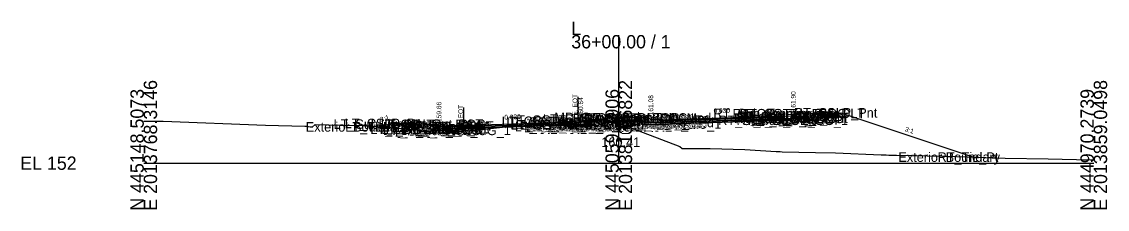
# Model space of a CAD drawing. Extents: x -26 to 4203, y -10 to 9526.
# Drawn here: x 1974.3 to 2202.8, y 5990.3 to 6029.7 of the extents above; entities that cross this region are included whole.
import ezdxf

# ---------------------------------------------------------------- set-up
doc = ezdxf.new("R2010")
doc.units = 0
for name, color, linetype in [('Default', 7, 'Continuous'), ('Exist CMT Pavement', 7, 'Continuous'), ('Exist Cross Section Cell', 7, 'Continuous'), ('Exist XS Center Line Elevation Label', 7, 'Continuous'), ('Exist XS Ground Line', 7, 'Continuous'), ('Prop CMT Conc Surface', 7, 'Continuous'), ('Prop CMT Concrete Structures', 7, 'Continuous'), ('Prop CMT Pvmt Course 1', 7, 'Continuous'), ('Prop CMT Pvmt Course 1 CG', 7, 'Continuous'), ('Prop CMT Pvmt Course 2', 7, 'Continuous'), ('Prop CMT Pvmt Course 3', 7, 'Continuous'), ('Prop CMT Pvmt Surface', 7, 'Continuous'), ('Prop CMT Slope Grass', 7, 'Continuous'), ('Prop CMT Subgrade Earthwork', 7, 'Continuous'), ('Prop XS Hydro Elevations', 7, 'Continuous'), ('Prop XS Label Text', 7, 'Continuous'), ('Prop XS SE Text', 7, 'Continuous'), ('Prop XS Side Slope Text', 7, 'Continuous'), ('Scratch_Level_0', 7, 'Continuous')]:
    doc.layers.add(name, color=color, linetype=linetype)

msp = doc.modelspace()

# ---------------------------------------------------------------- linework, layer by layer
at = {"layer": 'Exist CMT Pavement'}
for p, q in [((2079.53, 6007.97), (2082.4, 6008.24)), ((2082.4, 6008.24), (2085.23, 6008.5)), ((2085.23, 6008.5), (2088.01, 6008.71)), ((2088.01, 6008.71), (2089.25, 6008.81)), ((2067.33, 6006.71), (2068.41, 6006.78)), ((2068.41, 6006.78), (2071.22, 6007.09)), ((2071.22, 6007.09), (2074.28, 6007.44)), ((2074.28, 6007.44), (2076.82, 6007.69)), ((2076.82, 6007.69), (2078.38, 6007.85)), ((2078.38, 6007.85), (2079.53, 6007.97))]:
    msp.add_line(p, q, dxfattribs=at)
at = {"layer": 'Exist Cross Section Cell'}
for p, q in [((2100, 6000), (2100, 6026.93)), ((2000, 6000), (2100, 6000)), ((2100, 6000), (2200, 6000))]:
    msp.add_line(p, q, dxfattribs=at)
at = {"layer": 'Exist XS Ground Line'}
msp.add_lwpolyline([(2000, 6008.86), (2004.08, 6008.8), (2025.6, 6007.99), (2033.9, 6007.77), (2034.25, 6007.76), (2035.46, 6007.59), (2036.06, 6008.11), (2041.35, 6008), (2041.85, 6007.97), (2046.11, 6007.9), (2046.78, 6007.9), (2051.17, 6007.52), (2060.64, 6006.77), (2061.32, 6006.33), (2061.97, 6006.35), (2063.21, 6006.41), (2065.33, 6006.58), (2068.41, 6006.78), (2068.73, 6006.81), (2070.41, 6007), (2071.22, 6007.09), (2074.28, 6007.44), (2076.82, 6007.69), (2078.38, 6007.85), (2079.53, 6007.97), (2082.4, 6008.24), (2085.23, 6008.5), (2087.11, 6008.64), (2088.01, 6008.71), (2090.68, 6008.93), (2091.38, 6008.98), (2099.85, 6008.46), (2105.13, 6006.48), (2112.87, 6003.5), (2113.37, 6003.1), (2118.5, 6003.06), (2119.24, 6003.06), (2126.53, 6002.89), (2133.16, 6002.48), (2133.97, 6002.42), (2134.38, 6002.41), (2141.4, 6002.21), (2145.6, 6002.14), (2155.21, 6001.77), (2156.28, 6001.72), (2156.82, 6001.69), (2158.49, 6001.67), (2168.17, 6001.48), (2169.06, 6001.48), (2177.25, 6001.18), (2178.59, 6001.12), (2179.27, 6001.09), (2181.35, 6001.05), (2190.36, 6000.88), (2199.3, 6000.73), (2200, 6000.71)], dxfattribs=at)
at = {"layer": 'Prop CMT Conc Surface'}
for points in [[(2141.25, 6010.49), (2146.25, 6010.59)], [(2057.65, 6008.25), (2052.65, 6008.35)], [(2062.15, 6008.16), (2061.65, 6008.16)], [(2062.15, 6007.66), (2062.15, 6008.16)], [(2091.25, 6008.62), (2092, 6008.64), (2092, 6008.81), (2092.76, 6009.06)], [(2108.75, 6009.14), (2106.75, 6009.08), (2106.75, 6009.25), (2106, 6009.5)], [(2134.75, 6009.92), (2136.75, 6009.9)], [(2136.75, 6009.9), (2136.75, 6010.4), (2137.25, 6010.4)], [(2064.15, 6007.8), (2062.15, 6007.66)]]:
    msp.add_lwpolyline(points, dxfattribs=at)
at = {"layer": 'Prop CMT Concrete Structures'}
for points in [[(2146.25, 6010.59), (2141.25, 6010.49)], [(2141.25, 6010.49), (2141.25, 6010.16)], [(2146.25, 6010.26), (2146.25, 6010.59)], [(2052.65, 6008.02), (2052.65, 6008.35)], [(2052.65, 6008.35), (2057.65, 6008.25)], [(2057.65, 6008.25), (2057.65, 6007.92)], [(2062.15, 6008.16), (2061.65, 6008.16)], [(2061.65, 6008.16), (2061.65, 6007.14), (2064.15, 6007.22)], [(2062.15, 6007.66), (2062.15, 6008.16)], [(2091.25, 6008.62), (2092, 6008.64), (2092, 6008.81), (2092.76, 6009.06)], [(2091.25, 6008.03), (2091.25, 6008.62)], [(2092.76, 6009.06), (2092.76, 6008.08)], [(2108.75, 6009.14), (2106.75, 6009.08), (2106.75, 6009.25), (2106, 6009.5)], [(2106, 6009.5), (2106, 6008.48)], [(2106, 6008.48), (2108.75, 6008.56)], [(2108.75, 6008.56), (2108.75, 6009.14)], [(2134.75, 6009.92), (2136.75, 6009.9), (2136.75, 6010.4), (2137.25, 6010.4)], [(2137.25, 6010.4), (2137.25, 6009.41), (2134.75, 6009.34)], [(2134.75, 6009.34), (2134.75, 6009.92)], [(2141.25, 6010.16), (2146.25, 6010.26)], [(2057.65, 6007.92), (2052.65, 6008.02)], [(2064.15, 6007.8), (2062.15, 6007.66)], [(2064.15, 6007.22), (2064.15, 6007.8)], [(2092.76, 6008.08), (2091.25, 6008.03)]]:
    msp.add_lwpolyline(points, dxfattribs=at)
at = {"layer": 'Prop CMT Pvmt Course 1'}
for points in [[(2091.25, 6008.62), (2064.15, 6007.8)], [(2064.15, 6007.55), (2091.25, 6008.37), (2091.25, 6008.37)], [(2091.25, 6008.37), (2091.25, 6008.62)], [(2091.25, 6008.37), (2091.25, 6008.37)], [(2108.75, 6009.14), (2134.75, 6009.92)], [(2134.75, 6009.67), (2108.75, 6008.89)], [(2108.75, 6008.89), (2108.75, 6009.14)], [(2108.75, 6008.89), (2108.75, 6008.89), (2108.75, 6008.89)], [(2134.75, 6009.92), (2134.75, 6009.67)], [(2064.15, 6007.8), (2064.15, 6007.55)]]:
    msp.add_lwpolyline(points, dxfattribs=at)
at = {"layer": 'Prop CMT Pvmt Course 1 CG'}
for points in [[(2108.75, 6008.56), (2105.5, 6008.46), (2105.16, 6008.12)], [(2105.16, 6008.12), (2108.75, 6008.22)], [(2108.75, 6008.22), (2108.75, 6008.56)], [(2134.75, 6009.34), (2137.75, 6009.43), (2138.07, 6009.11)], [(2134.75, 6009.01), (2134.75, 6009.34)], [(2138.07, 6009.11), (2134.75, 6009.01)], [(2064.15, 6007.22), (2061.15, 6007.13), (2060.81, 6006.79)], [(2060.81, 6006.79), (2064.15, 6006.89)], [(2064.15, 6006.89), (2064.15, 6007.22)], [(2093.58, 6007.77), (2089.25, 6007.64)], [(2091.25, 6008.03), (2093.26, 6008.09), (2093.58, 6007.77)], [(2091.25, 6007.7), (2091.25, 6008.03)]]:
    msp.add_lwpolyline(points, dxfattribs=at)
at = {"layer": 'Prop CMT Pvmt Course 2'}
for points in [[(2091.25, 6008.37), (2064.15, 6007.55)], [(2091.25, 6008.03), (2091.25, 6008.37)], [(2108.75, 6008.89), (2134.75, 6009.67)], [(2134.75, 6009.34), (2108.75, 6008.56)], [(2108.75, 6008.56), (2108.75, 6008.89)], [(2134.75, 6009.67), (2134.75, 6009.34)], [(2064.15, 6007.22), (2091.25, 6008.03)], [(2064.15, 6007.55), (2064.15, 6007.22)]]:
    msp.add_lwpolyline(points, dxfattribs=at)
at = {"layer": 'Prop CMT Pvmt Course 3'}
for points in [[(2108.75, 6008.56), (2134.75, 6009.34)], [(2134.75, 6009.01), (2108.75, 6008.22)], [(2108.75, 6008.22), (2108.75, 6008.56)], [(2134.75, 6009.34), (2134.75, 6009.01)], [(2091.25, 6008.03), (2064.15, 6007.22)], [(2064.15, 6007.22), (2064.15, 6006.89)], [(2064.15, 6006.89), (2067.33, 6006.98)]]:
    msp.add_lwpolyline(points, dxfattribs=at)
at = {"layer": 'Prop CMT Pvmt Surface'}
for points in [[(2091.25, 6008.62), (2064.15, 6007.8)], [(2108.75, 6009.14), (2134.75, 6009.92)]]:
    msp.add_lwpolyline(points, dxfattribs=at)
at = {"layer": 'Prop CMT Slope Grass'}
for points in [[(2137.25, 6010.4), (2146.75, 6010.59)], [(2146.75, 6010.59), (2174.72, 6001.27)], [(2052.15, 6008.35), (2049.97, 6007.63)], [(2061.65, 6008.16), (2052.15, 6008.35)], [(2092.76, 6009.06), (2099.38, 6009.63)], [(2106, 6009.5), (2099.38, 6009.63)]]:
    msp.add_lwpolyline(points, dxfattribs=at)
at = {"layer": 'Prop CMT Subgrade Earthwork'}
for p, q in [((2089.25, 6007.64), (2089.25, 6008.81)), ((2067.33, 6006.98), (2067.33, 6006.71))]:
    msp.add_line(p, q, dxfattribs=at)
for points in [[(2134.75, 6009.01), (2138.07, 6009.11), (2139.41, 6010.45)], [(2064.15, 6006.89), (2060.81, 6006.79), (2059.39, 6008.21)], [(2095.07, 6009.26), (2093.58, 6007.77)], [(2103.73, 6009.54), (2105.16, 6008.12)], [(2105.16, 6008.12), (2108.75, 6008.22)], [(2108.75, 6008.22), (2134.75, 6009.01)], [(2108.75, 6008.22), (2108.75, 6008.22)], [(2108.75, 6008.22), (2108.75, 6008.22)], [(2134.75, 6009.01), (2134.75, 6009.01)], [(2067.33, 6006.98), (2064.15, 6006.89)], [(2064.15, 6006.89), (2064.15, 6006.89)], [(2093.58, 6007.77), (2089.25, 6007.64)], [(2091.25, 6007.7), (2091.25, 6007.7)], [(2091.25, 6007.7), (2091.25, 6007.7)]]:
    msp.add_lwpolyline(points, dxfattribs=at)
at = {"layer": 'Prop XS Label Text'}
for p, q in [((2091.38, 6013.98), (2091.38, 6008.98)), ((2067.33, 6011.71), (2067.33, 6006.71))]:
    msp.add_line(p, q, dxfattribs=at)

# ---------------------------------------------------------------- texts
at = {"layer": 'Default'}
msp.add_text('-', height=0.0001, dxfattribs=at).set_placement((2000, 6000))
at = {"layer": 'Exist Cross Section Cell'}
for s, p in [('L', (2090, 6026.93)), ('36+00.00 / 1', (2090, 6024.13)), ('EL 152', (1974, 5998.6))]:
    msp.add_text(s, height=2.8, dxfattribs=at).set_placement(p)
for s, p in [('E 2013768.3146', (2002.8, 5990)), ('E 2013813.6822', (2102.8, 5990)), ('E 2013859.0498', (2202.8, 5990)), ('N 445148.5073', (2000, 5990)), ('N 445059.3906', (2100, 5990)), ('N 444970.2739', (2200, 5990))]:
    msp.add_text(s, height=2.8, rotation=90, dxfattribs=at).set_placement(p)
at = {"layer": 'Exist XS Center Line Elevation Label'}
msp.add_text('160.41', height=2, dxfattribs=at).set_placement((2096.32, 6003.41))
at = {"layer": 'Prop XS Hydro Elevations'}
for s, p in [('159.66', (2062.65, 6008.66)), ('160.64', (2092.5, 6009.64)), ('161.08', (2107.25, 6010.08)), ('161.90', (2137.25, 6010.9))]:
    msp.add_text(s, height=1, rotation=90, dxfattribs=at).set_placement(p)
at = {"layer": 'Prop XS Label Text'}
for p in [(2091.28, 6010), (2067.23, 6007.73)]:
    msp.add_text('E. EOT', height=1, rotation=90, dxfattribs=at).set_placement(p)
at = {"layer": 'Prop XS SE Text'}
for rotation, p in [(1.7184, (2119.97, 6010.48)), (1.7185, (2075.92, 6009.16))]:
    msp.add_text('0.030', height=1, rotation=rotation, dxfattribs=at).set_placement(p)
at = {"layer": 'Prop XS Side Slope Text'}
for rotation, p in [(18.4349, (2049.95, 6008.64)), (341.5651, (2160.13, 6006.76))]:
    msp.add_text('3:1', height=1, rotation=rotation, dxfattribs=at).set_placement(p)
at = {"layer": 'Scratch_Level_0'}
for s, p in [('MD_Crown Point', (2086.45, 6008.63)), ('RT_CG_Top_BOC_Med', (2090.35, 6008.5)), ('RT_CG_Top_BOC In', (2091.97, 6008.5)), ('RT_Sub_DLT_In', (2092.63, 6008.54)), ('RT_Sub_Trench_Out_DLT', (2119.93, 6009.45)), ('RT_CG_Top_Face', (2123.96, 6009.4)), ('RT_CG1_Shelf_Out', (2124.25, 6008.43)), ('RT_PV2_OEOT', (2124.88, 6008.67)), ('RT_CG_Top_Gut', (2124.94, 6008.9)), ('RT_PV1_OEOT', (2125.44, 6008.92)), ('RT_CG_Top_BOC', (2125.49, 6009.4)), ('RT_CG_Bot_BOC', (2125.52, 6008.41)), ('RT_CSLP_Pnt', (2136.88, 6009.59)), ('Exterior Boundary', (2034.11, 6006.63)), ('LT_Sub_Trench_Out_DLT', (2039.95, 6007.21)), ('LT_CSLP_Pnt', (2042.32, 6007.35)), ('LT_Tie_Pt', (2042.41, 6006.63)), ('LT_CG1_Shelf_Out', (2047.7, 6006.13)), ('LT_CG_Top_Face', (2049.41, 6007.16)), ('LT_CG_Top_BOC', (2049.93, 6007.16)), ('LT_CG_Bot_BOC', (2049.97, 6006.14)), ('LT_CG_Top_Gut', (2050.39, 6006.66)), ('LT_CG_Bot_IE', (2054.07, 6006.22)), ('LT_PV2_OEOT', (2054.33, 6006.55)), ('LT_PV3_OEOT', (2054.33, 6006.22)), ('LT_PV1_OEOT', (2054.89, 6006.8)), ('LT_CG_Top_Face_Med', (2075.37, 6007.81)), ('LT_CG_Top_Gut_Med', (2076.35, 6007.64)), ('LT_CG_Top_BOC_Med', (2077.15, 6008.06)), ('LT_CG_Bot_BOC_Med', (2077.19, 6007.08)), ('LT_CG_Bot_IE_Med', (2077.31, 6007.03)), ('LT_Sub_IEOT_CG_1', (2078.12, 6006.7)), ('LT_Sub_OEEOP', (2080.46, 6006.7)), ('LT_PV2_OEEOP', (2080.56, 6007.37)), ('LT_PV3_OEEOP', (2080.56, 6007.03)), ('LT_Sub_IEEOP', (2081.11, 6006.7)), ('LT_PV2_IEEOP', (2081.2, 6007.37)), ('LT_CG1_Shelf_In', (2081.43, 6007.09)), ('LT_Sub_PGL', (2082.37, 6006.7)), ('LT_PV2_PGL', (2082.46, 6007.37)), ('LT_PV1_PGL', (2083.03, 6007.62)), ('LT_Sub_DLT_In', (2084.02, 6008.26)), ('LT_Sub_IEOP', (2084.34, 6006.77)), ('RT_CG_Bot BOC In', (2091.84, 6007.48)), ('RT_CG_Top FOC In', (2092.61, 6008.25)), ('RT_CG_Top_Gut In', (2092.64, 6008.08)), ('RT_CG1_Shelf_In', (2093.63, 6007.46)), ('RT_CG_Bot_IE_Med', (2094.77, 6007.56)), ('RT_Sub_IEOT_CG_1', (2095.57, 6007.22)), ('RT_Sub_IEOP', (2095.87, 6007.12)), ('RT_Sub_OEEOP', (2097.92, 6007.22)), ('RT_PV2_OEEOP', (2098.01, 6007.89)), ('RT_PV3_OEEOP', (2098.01, 6007.56)), ('RT_Sub_IEEOP', (2098.56, 6007.22)), ('RT_PV2_IEEOP', (2098.66, 6007.89)), ('RT_Sub_PGL', (2099.82, 6007.22)), ('RT_PV2_PGL', (2099.92, 6007.89)), ('RT_PV1_PGL', (2100.48, 6008.14)), ('RT_Sub_OEOT_CG_1', (2120.92, 6008.01)), ('RT_CG_Bot_IE', (2124.62, 6008.34)), ('RT_Sub_OEOT', (2124.78, 6008.01)), ('RT_PV3_OEOT', (2124.88, 6008.34)), ('RT_Sub_OEOP', (2128.14, 6008.11)), ('LT_Sub_OEOT_CG_1', (2050.37, 6005.89)), ('LT_Sub_OEOP', (2050.92, 6005.79)), ('LT_Sub_OEOT', (2054.23, 6005.89)), ('Exterior Boundary', (2158.86, 6000.27)), ('RT_Tie_Pt', (2167.11, 6000.27))]:
    msp.add_text(s, height=2, dxfattribs=at).set_placement(p)

doc.saveas('drawing.dxf')
